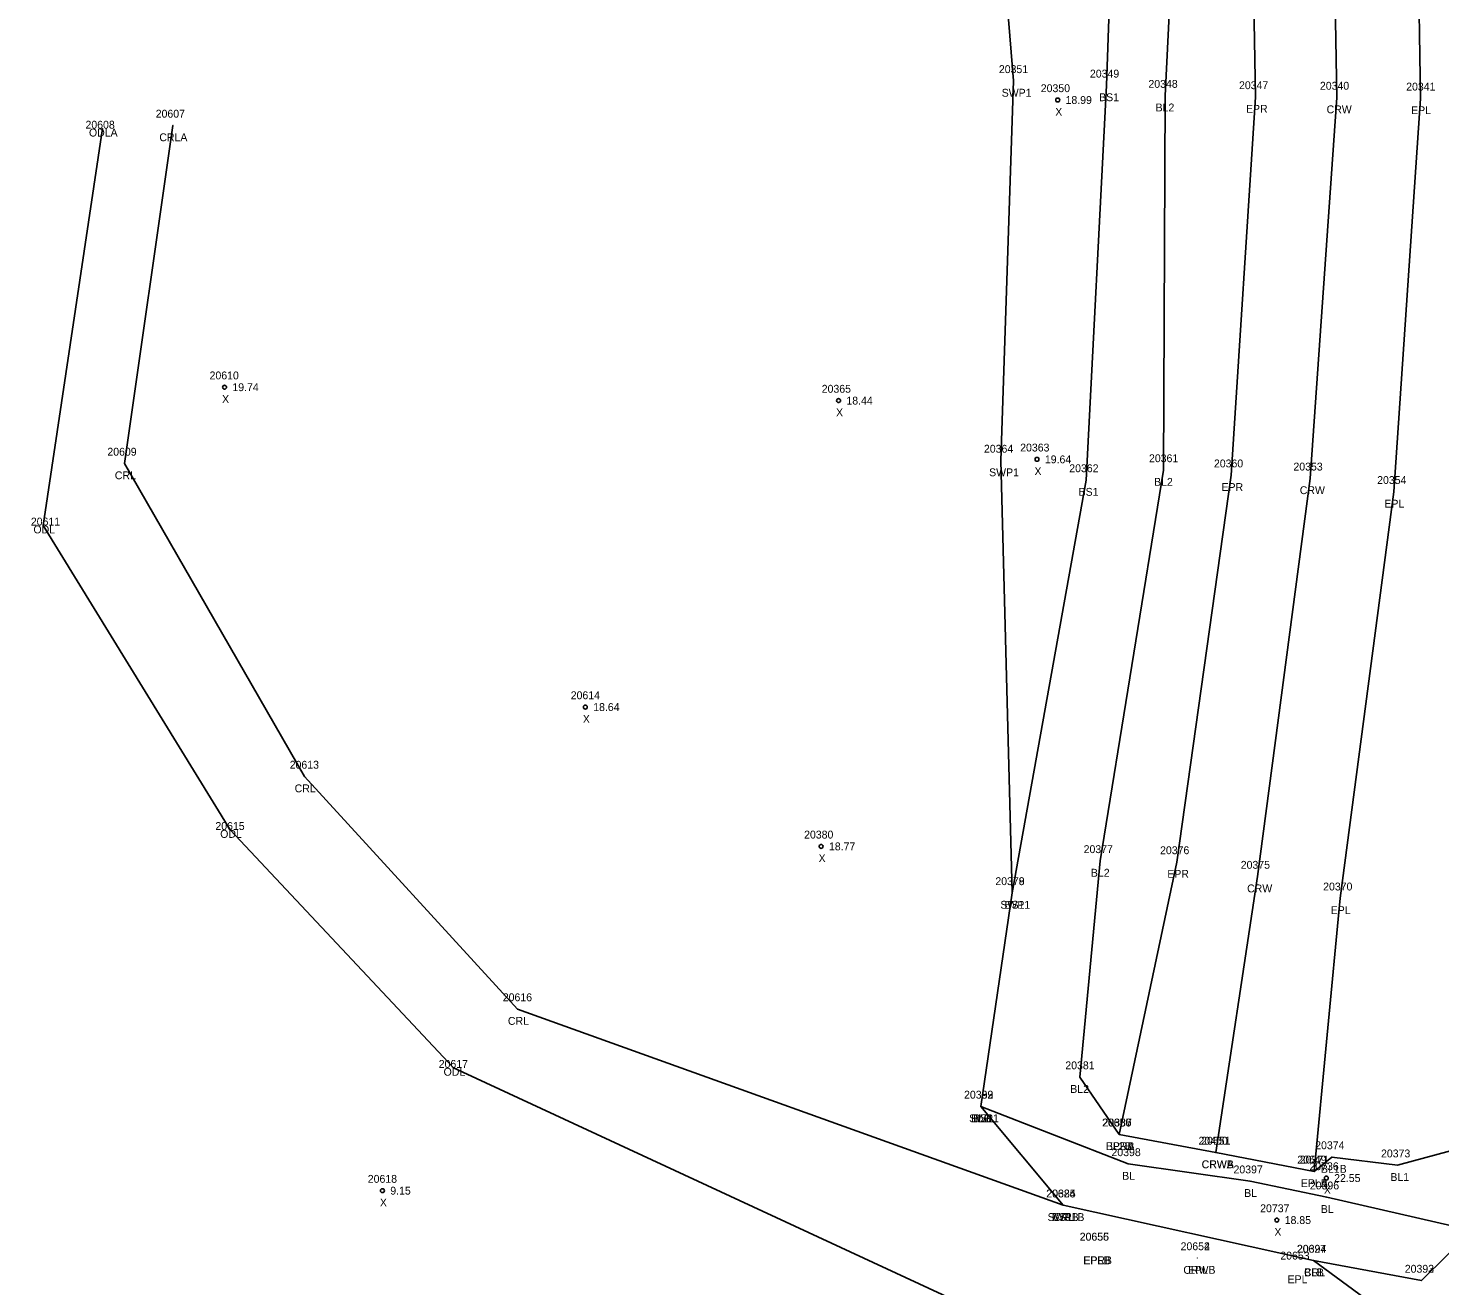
# Model space of a CAD drawing. Extents: x 2432729 to 2433340, y 684958 to 688103.
# Drawn here: x 2432989.3 to 2433168.9, y 686061.9 to 686221.7 of the extents above; entities that cross this region are included whole.
import ezdxf

# ---------------------------------------------------------------- set-up
doc = ezdxf.new("R2010")
doc.units = 0
for name, color, linetype in [('Default', 7, 'Continuous'), ('RD_DTM_BkLn1', 7, 'Continuous'), ('RD_DTM_BkLn2', 7, 'Continuous'), ('RD_EX_H2O', 7, 'Continuous'), ('RD_EX_H2O_txCode', 7, 'Continuous'), ('RD_EX_Road', 7, 'Continuous'), ('RD_EX_Road_txCode', 7, 'Continuous'), ('RD_Sketch8', 7, 'Continuous'), ('RD_SMD_Locator', 7, 'Continuous'), ('RD_SMD_Misc', 7, 'Continuous')]:
    doc.layers.add(name, color=color, linetype=linetype)

msp = doc.modelspace()

# ---------------------------------------------------------------- linework, layer by layer
at = {"layer": 'Default'}
msp.add_circle((2433138.04, 686065.41), 0.001, dxfattribs=at)
at = {"layer": 'RD_DTM_BkLn1'}
for points in [[(2432926.02, 687213.66), (2432924.35, 687158.94), (2432925.68, 687108.84), (2432939.7, 687000.92), (2432956.93, 686927.39), (2432975, 686866.8), (2433007.19, 686769.33), (2433041.66, 686669.67), (2433075.97, 686569.51), (2433108.49, 686474.01), (2433123.82, 686426.48), (2433137.99, 686374.7), (2433148.76, 686320.1), (2433154.8, 686269.16), (2433155.78, 686212.93), (2433152.37, 686164.52), (2433145.67, 686113.9), (2433140.38, 686078.83)], [(2432898.98, 687049.37), (2432906.9, 687044.55), (2432919.33, 686997.25), (2432938.84, 686920.72), (2432957.15, 686862.46), (2432990.45, 686763.71), (2433024.84, 686664.51), (2433058.68, 686562.8), (2433090.41, 686467.11), (2433107.21, 686420.87), (2433120.26, 686369.86), (2433132.05, 686313.5), (2433136.59, 686267.4), (2433133.92, 686213.17), (2433133.74, 686165.58), (2433125.69, 686115.89), (2433123.08, 686088.41), (2433128.09, 686081.14)], [(2433121.01, 686546.89), (2433138.81, 686483.59), (2433156.33, 686436.44), (2433172.33, 686382.63), (2433186.16, 686325.49), (2433196.85, 686279.41), (2433196.3, 686212.3), (2433190.98, 686162.16), (2433188.39, 686102.75), (2433180.42, 686073.48), (2433172.96, 686068.93), (2433166.53, 686062.55), (2433152.82, 686065.09)], [(2433099.45, 686534.09), (2433116.42, 686534.99), (2433132.92, 686481.52), (2433149.46, 686435.57), (2433165.09, 686381.24), (2433180.28, 686324.44), (2433185.06, 686269.22), (2433188.28, 686211.65), (2433183.39, 686161.81), (2433176.18, 686106.19), (2433174.91, 686080.31), (2433163.5, 686077.21), (2433155.14, 686078.25)], [(2433172.96, 686068.93), (2433154.49, 686073.14), (2433144.74, 686075.18), (2433129.23, 686077.37), (2433110.48, 686084.68)], [(2433155.14, 686078.25), (2433152.88, 686076.43), (2433140.38, 686078.83), (2433128.09, 686081.14)]]:
    msp.add_lwpolyline(points, dxfattribs=at)
at = {"layer": 'RD_DTM_BkLn2'}
msp.add_lwpolyline([(2432916.74, 686973.9), (2432925.37, 686926.35), (2432950.18, 686859.06), (2432982.46, 686761.59), (2433017.67, 686659.38), (2433053.8, 686561.16), (2433080.54, 686460.75), (2433098.39, 686424.64), (2433113.62, 686368.79), (2433123.31, 686312.63), (2433128.29, 686266.56), (2433126.49, 686214.47), (2433123.88, 686164.31), (2433114.46, 686111.82), (2433110.48, 686084.68), (2433120.95, 686072.12)], dxfattribs=at)
at = {"layer": 'RD_EX_H2O'}
for points in [[(2433059.53, 686447.22), (2433075.46, 686410.47), (2433059.4, 686367.42), (2433076.9, 686309.73), (2433110.63, 686264.52), (2433114.63, 686215.04), (2433113.03, 686166.79), (2433114.46, 686111.82), (2433110.48, 686084.68), (2433120.95, 686072.12)], [(2433227.48, 686289.61), (2433196.85, 686279.41), (2433196.3, 686212.3), (2433190.98, 686162.16), (2433188.39, 686102.75), (2433180.42, 686073.48), (2433172.96, 686068.93), (2433166.53, 686062.55)], [(2432998.81, 686208.98), (2432991.26, 686158.53), (2433015.01, 686119.83), (2433043.41, 686089.59), (2433120.85, 686053.69), (2433150.58, 686051.7), (2433203.32, 686017.95), (2433331.51, 685987.84)], [(2433007.74, 686209.38), (2433001.59, 686166.41), (2433024.46, 686126.62), (2433051.58, 686097.06), (2433120.95, 686072.12), (2433152.82, 686065.09), (2433205.51, 686026.38), (2433335.15, 685993.61)]]:
    msp.add_lwpolyline(points, dxfattribs=at)
at = {"layer": 'RD_EX_Road'}
for points in [[(2432915.64, 687215.4), (2432913.86, 687159.12), (2432915.08, 687107.55), (2432919.97, 687053.4), (2432928.7, 686998.89), (2432946.77, 686924.59), (2432964.57, 686864), (2432997.3, 686766.34), (2433031.44, 686666.38), (2433066.06, 686565.78), (2433098.73, 686469.74), (2433113.88, 686422.91), (2433127.93, 686372.14), (2433139.1, 686314.76), (2433144.47, 686268.02), (2433145.44, 686213), (2433142.32, 686164.92), (2433135.44, 686115.75), (2433128.09, 686081.14)], [(2433070.23, 686619.38), (2433072.02, 686607.31), (2433079.53, 686592.62), (2433082.99, 686582.32), (2433082.14, 686577.64), (2433086.96, 686563.7), (2433088.99, 686562.5), (2433099.45, 686534.09), (2433118.26, 686478), (2433133.83, 686430.29), (2433148.35, 686377.56), (2433159.33, 686322.19), (2433165.5, 686270.06), (2433166.43, 686212.82), (2433163.02, 686162.81), (2433156.19, 686111.14), (2433152.88, 686076.43)]]:
    msp.add_lwpolyline(points, dxfattribs=at)
at = {"layer": 'RD_SMD_Locator'}
for centre, radius in [((2433114.63, 686215.04), 0.001), ((2433126.49, 686214.47), 0.001), ((2433120.27, 686212.62), 0.25), ((2433133.92, 686213.17), 0.001), ((2433145.44, 686213), 0.001), ((2433155.78, 686212.93), 0.001), ((2433166.43, 686212.82), 0.001), ((2432998.81, 686208.98), 0.001), ((2433007.74, 686209.38), 0.001), ((2433014.31, 686176.11), 0.25), ((2433092.4, 686174.41), 0.25), ((2433001.59, 686166.41), 0.001), ((2433113.03, 686166.79), 0.001), ((2433117.64, 686166.94), 0.25), ((2433123.88, 686164.31), 0.001), ((2433133.74, 686165.58), 0.001), ((2433142.32, 686164.92), 0.001), ((2433152.37, 686164.52), 0.001), ((2433163.02, 686162.81), 0.001), ((2432991.26, 686158.53), 0.001), ((2433060.2, 686135.45), 0.25), ((2433024.46, 686126.62), 0.001), ((2433015.01, 686119.83), 0.001), ((2433090.18, 686117.74), 0.25), ((2433125.69, 686115.89), 0.001), ((2433135.44, 686115.75), 0.001), ((2433145.67, 686113.9), 0.001), ((2433114.46, 686111.82), 0.001), ((2433114.46, 686111.82), 0.001), ((2433156.19, 686111.14), 0.001), ((2433051.58, 686097.06), 0.001), ((2433043.41, 686089.59), 0.001), ((2433123.08, 686088.41), 0.001), ((2433110.48, 686084.68), 0.001), ((2433110.48, 686084.68), 0.001), ((2433110.48, 686084.68), 0.001), ((2433128.09, 686081.14), 0.001), ((2433128.09, 686081.14), 0.001), ((2433128.09, 686081.14), 0.001), ((2433140.38, 686078.83), 0.001), ((2433140.38, 686078.83), 0.001), ((2433155.14, 686078.25), 0.001), ((2433129.23, 686077.37), 0.001), ((2433152.88, 686076.43), 0.001), ((2433152.88, 686076.43), 0.001), ((2433163.5, 686077.21), 0.001), ((2433144.74, 686075.18), 0.001), ((2433154.43, 686075.58), 0.25), ((2433034.39, 686073.98), 0.25), ((2433154.49, 686073.14), 0.001), ((2433120.95, 686072.12), 0.001), ((2433120.95, 686072.12), 0.001), ((2433120.95, 686072.12), 0.001), ((2433148.14, 686070.24), 0.25), ((2433152.82, 686065.09), 0.001), ((2433152.82, 686065.09), 0.001), ((2433166.53, 686062.55), 0.001), ((2433166.53, 686062.55), 0.001)]:
    msp.add_circle(centre, radius, dxfattribs=at)

# ---------------------------------------------------------------- texts
at = {"layer": 'RD_EX_H2O_txCode'}
for s, p in [('20351', (2433112.79, 686216.04)), ('SWP1', (2433113.15, 686213.04)), ('20607', (2433005.56, 686210.38)), ('20608', (2432996.63, 686208.98)), ('ODLA', (2432997.07, 686207.98)), ('CRLA', (2433006.02, 686207.38)), ('20609', (2432999.41, 686167.41)), ('20364', (2433110.89, 686167.79)), ('CRL', (2433000.36, 686164.41)), ('SWP1', (2433111.55, 686164.79)), ('20611', (2432989.68, 686158.53)), ('ODL', (2432990.01, 686157.53)), ('20613', (2433022.6, 686127.62)), ('CRL', (2433023.23, 686124.62)), ('20615', (2433013.15, 686119.83)), ('ODL', (2433013.76, 686118.83)), ('20379', (2433112.34, 686112.82)), ('SWP1', (2433112.98, 686109.82)), ('20616', (2433049.7, 686098.06)), ('CRL', (2433050.35, 686095.06)), ('20617', (2433041.55, 686089.59)), ('ODL', (2433042.17, 686088.59)), ('20382', (2433108.36, 686085.68)), ('SWP1', (2433109, 686082.68)), ('20624', (2433118.81, 686073.12)), ('20384', (2433118.83, 686073.12)), ('SWP1B', (2433118.99, 686070.12)), ('CRL', (2433119.72, 686070.12)), ('20627', (2433150.68, 686066.09)), ('CRL', (2433151.6, 686063.09)), ('20392', (2433164.41, 686063.55))]:
    msp.add_text(s, height=1, dxfattribs=at).set_placement(p)
at = {"layer": 'RD_EX_Road_txCode'}
for s, p in [('20347', (2433143.33, 686214)), ('20341', (2433164.59, 686213.82)), ('EPR', (2433144.22, 686211)), ('EPL', (2433165.22, 686210.82)), ('20360', (2433140.14, 686165.92)), ('20354', (2433160.9, 686163.81)), ('EPR', (2433141.1, 686162.92)), ('EPL', (2433161.82, 686160.81)), ('20376', (2433133.29, 686116.75)), ('EPR', (2433134.21, 686113.75)), ('20370', (2433154.03, 686112.14)), ('EPL', (2433154.99, 686109.14)), ('20650', (2433125.91, 686082.14)), ('20387', (2433125.97, 686082.14)), ('EPRA', (2433126.37, 686079.14)), ('EPRB', (2433126.39, 686079.14)), ('20649', (2433150.74, 686077.43)), ('20371', (2433151.05, 686077.43)), ('EPLA', (2433151.19, 686074.43)), ('EPLB', (2433151.2, 686074.43)), ('20656', (2433123.06, 686067.63)), ('20655', (2433123.08, 686067.63)), ('20654', (2433135.9, 686066.41)), ('EPRB', (2433123.52, 686064.63)), ('EPLB', (2433123.55, 686064.63)), ('20653', (2433148.58, 686065.22)), ('EPL', (2433136.84, 686063.41)), ('EPL', (2433149.51, 686062.22))]:
    msp.add_text(s, height=1, dxfattribs=at).set_placement(p)
at = {"layer": 'RD_Sketch8'}
for s, p in [('20350', (2433118.12, 686213.62)), ('18.99', (2433121.27, 686212.12)), ('X', (2433119.96, 686210.62)), ('20610', (2433012.41, 686177.11)), ('X', (2433014, 686174.11)), ('19.74', (2433015.31, 686175.61)), ('20365', (2433090.26, 686175.41)), ('18.44', (2433093.4, 686173.91)), ('X', (2433092.08, 686172.41)), ('20363', (2433115.5, 686167.94)), ('X', (2433117.32, 686164.94)), ('19.64', (2433118.64, 686166.44)), ('20614', (2433058.34, 686136.45)), ('18.64', (2433061.2, 686134.95)), ('X', (2433059.88, 686133.45)), ('20380', (2433088.02, 686118.74)), ('18.77', (2433091.18, 686117.24)), ('X', (2433089.86, 686115.74)), ('20736', (2433152.29, 686076.58)), ('20618', (2433032.53, 686074.98)), ('9.15', (2433035.39, 686073.48)), ('X', (2433154.12, 686073.58)), ('22.55', (2433155.43, 686075.08)), ('X', (2433034.07, 686071.98)), ('20737', (2433146.02, 686071.24)), ('18.85', (2433149.14, 686069.74)), ('X', (2433147.83, 686068.24))]:
    msp.add_text(s, height=1, dxfattribs=at).set_placement(p)
at = {"layer": 'RD_SMD_Misc'}
for s, p in [('20349', (2433124.37, 686215.47)), ('20348', (2433131.81, 686214.17)), ('20340', (2433153.62, 686213.93)), ('BS1', (2433125.54, 686212.47)), ('BL2', (2433132.72, 686211.17)), ('CRW', (2433154.47, 686210.93)), ('20362', (2433121.74, 686165.31)), ('20361', (2433131.88, 686166.58)), ('20353', (2433150.25, 686165.52)), ('BL2', (2433132.53, 686163.58)), ('BS1', (2433122.93, 686162.31)), ('CRW', (2433151.06, 686162.52)), ('20377', (2433123.57, 686116.89)), ('20375', (2433143.55, 686114.9)), ('20378', (2433112.34, 686112.82)), ('BL2', (2433124.49, 686113.89)), ('CRW', (2433144.36, 686111.9)), ('BS1', (2433113.51, 686109.82)), ('20381', (2433121.24, 686089.41)), ('BL2', (2433121.87, 686086.41)), ('20383', (2433108.36, 686085.68)), ('20399', (2433108.36, 686085.68)), ('BLB', (2433109.25, 686082.68)), ('BS1', (2433109.53, 686082.68)), ('20386', (2433125.94, 686082.14)), ('BL2B', (2433126.41, 686079.14)), ('20400', (2433138.18, 686079.83)), ('20651', (2433138.52, 686079.83)), ('20374', (2433153.02, 686079.25)), ('20398', (2433127.11, 686078.37)), ('20373', (2433161.39, 686078.21)), ('BL', (2433128.47, 686075.37)), ('CRWA', (2433138.57, 686076.83)), ('CRWB', (2433138.59, 686076.83)), ('20397', (2433142.63, 686076.18)), ('BL1B', (2433153.75, 686076.25)), ('BL1', (2433162.58, 686075.21)), ('20396', (2433152.34, 686074.14)), ('20385', (2433118.83, 686073.12)), ('BL', (2433143.99, 686073.18)), ('BS1B', (2433119.53, 686070.12)), ('BL', (2433153.73, 686071.14)), ('20652', (2433135.9, 686066.41)), ('20394', (2433150.71, 686066.09)), ('CRWB', (2433136.25, 686063.41)), ('BLB', (2433151.6, 686063.09)), ('20393', (2433164.41, 686063.55))]:
    msp.add_text(s, height=1, dxfattribs=at).set_placement(p)

doc.saveas('drawing.dxf')
